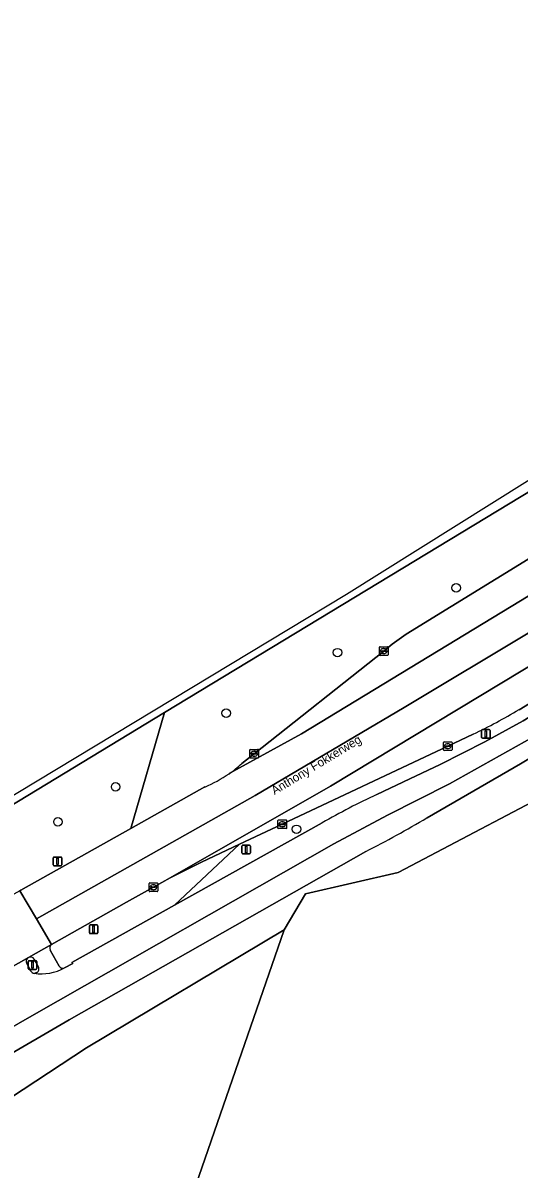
# Model space of a CAD drawing. Extents: x 158132 to 159664, y 385256 to 387218.
# Drawn here: x 158673.7 to 158730.9, y 387074.1 to 387206.2 of the extents above; entities that cross this region are included whole.
import ezdxf

# ---------------------------------------------------------------- set-up
doc = ezdxf.new("R2010")
doc.units = 0
for name, color, linetype in [('IMGEO_Berm_groen', 7, 'Continuous'), ('IMGEO_Boom', 7, 'Continuous'), ('IMGEO_Fietspad_gesloten', 7, 'Continuous'), ('IMGEO_Gemengd_bos', 7, 'Continuous'), ('IMGEO_Groenvoorziening', 7, 'Continuous'), ('IMGEO_Kolk', 7, 'Continuous'), ('IMGEO_Lichtmast', 7, 'Continuous'), ('IMGEO_Openbare_ruimte_label', 7, 'Continuous'), ('IMGEO_Rijbaan_regionaal_gesloten', 7, 'Continuous'), ('IMGEO_Verkeersbordpaal', 7, 'Continuous'), ('IMGEO_Verkeerseiland_open', 7, 'Continuous'), ('IMGEO_Verkeersregelinstallatiepaal', 7, 'Continuous'), ('IMGEO_Voetpad_gesloten', 7, 'Continuous'), ('IMGEO_Voetpad_open', 7, 'Continuous')]:
    doc.layers.add(name, color=color, linetype=linetype)

msp = doc.modelspace()

# ---------------------------------------------------------------- linework, layer by layer
at = {"layer": 'IMGEO_Berm_groen'}
for points in [[(158791.92, 387181.1), (158796.99, 387191.8), (158761.35, 387169.93), (158690.06, 387126.75), (158686.16, 387113.36), (158694.7, 387118.16)], [(158698.94, 387120.87), (158700.39, 387122), (158715.32, 387133.83), (158716.27, 387134.61), (158717.89, 387135.77), (158733.46, 387145.34), (158750.96, 387156.02), (158791.92, 387181.1)], [(158772.34, 387150.79), (158775.89, 387153.01), (158780.92, 387155.97), (158809.62, 387171.75), (158799.54, 387169.08), (158778.35, 387156.07), (158758.93, 387144.19), (158740.98, 387133.23), (158730.91, 387127.07)], [(158714.52, 387117.31), (158718.31, 387119.1), (158721.8, 387120.75), (158726.96, 387123.38), (158731.39, 387125.77), (158772.34, 387150.79)], [(158690.06, 387126.75), (158669.08, 387114.04)], [(158673.36, 387106.21), (158673.51, 387106.27), (158686.16, 387113.36), (158690.06, 387126.75)], [(158725.63, 387124.25), (158722.68, 387122.87), (158703.62, 387113.86), (158698.7, 387111.56), (158691.19, 387104.54), (158708.21, 387114.02)], [(158698.7, 387111.56), (158694.31, 387109.51), (158690.71, 387107.7), (158688.77, 387106.6), (158685.66, 387104.87), (158677.03, 387100.01)], [(158678.54, 387097.3), (158679.47, 387097.81), (158679.38, 387097.95), (158691.19, 387104.54), (158698.7, 387111.56)], [(158676.88, 387099.35), (158677.91, 387097.51)]]:
    msp.add_lwpolyline(points, dxfattribs=at)
for centre, radius, start, end in [((158697.65, 387183.04), 65.1, 295.4546, 300.7185), ((158689.33, 387131.23), 14.14, 305.281, 312.8621), ((158689.33, 387131.21), 14.11, 292.3448, 305.3067), ((158750.8, 387039.92), 85.47, 115.1204, 119.8902), ((158677.37, 387099.59), 0.541, 128.4825, 206.3868), ((158678.34, 387097.77), 0.5, 210.6116, 292.904)]:
    msp.add_arc(centre, radius, start, end, dxfattribs=at)
at = {"layer": 'IMGEO_Boom'}
for centre in [(158723.65, 387141.12), (158709.99, 387133.65), (158697.15, 387126.67), (158684.41, 387118.18), (158677.77, 387114.14), (158705.26, 387113.29)]:
    msp.add_circle(centre, 0.489, dxfattribs=at)
at = {"layer": 'IMGEO_Fietspad_gesloten'}
for points in [[(158709.57, 387111.62), (158715.76, 387114.9), (158722.89, 387118.52), (158732.48, 387123.89), (158776.89, 387150.89), (158823.8, 387176.6), (158822.27, 387178.97), (158818.13, 387176.42), (158809.62, 387171.75), (158780.92, 387155.97), (158775.89, 387153.01), (158772.34, 387150.79), (158731.39, 387125.77), (158726.96, 387123.38), (158721.8, 387120.75), (158718.31, 387119.1), (158714.52, 387117.31)], [(158708.21, 387114.02), (158691.19, 387104.54), (158679.38, 387097.95), (158679.47, 387097.81), (158678.54, 387097.3)], [(158490.61, 386969.27), (158499.21, 386977.39), (158500, 386978.13), (158506.55, 386984.13), (158513.13, 386989.79), (158514.13, 386990.65), (158525.95, 387000), (158529.92, 387003.03), (158546.1, 387014.7), (158573.79, 387032.7), (158595.96, 387046.32), (158640.94, 387072.39), (158675.02, 387091.93), (158709.57, 387111.62)], [(158674.36, 387098.5), (158672.06, 387097.2), (158671.67, 387096.98)], [(158674.64, 387096.95), (158674.17, 387097.81)]]:
    msp.add_lwpolyline(points, dxfattribs=at)
for centre, radius, start, end in [((158750.8, 387039.92), 85.47, 115.1204, 119.8902), ((158674.61, 387098.06), 0.503, 119.8027, 209.4603), ((158675.05, 387097.13), 0.447, 204.2706, 265.9912), ((158675.85, 387102.27), 5.64, 261.5723, 298.4604)]:
    msp.add_arc(centre, radius, start, end, dxfattribs=at)
at = {"layer": 'IMGEO_Gemengd_bos'}
for points in [[(158826.07, 387175.67), (158796.65, 387159.48), (158797.02, 387156.73), (158769.67, 387143.32), (158742.44, 387125.91), (158738.31, 387119.52), (158716.99, 387108.3), (158706.29, 387105.85), (158703.82, 387101.71), (158689.82, 387061.16), (158690.52, 387056.33), (158694.37, 387054.05)], [(158687.81, 387060.41), (158689.82, 387061.16), (158703.82, 387101.71), (158681.04, 387088.11), (158663.51, 387076.57), (158660.41, 387074.96), (158660.01, 387075.7), (158644.04, 387067.33), (158614.63, 387050.48), (158601.87, 387043.7), (158647.81, 386955.65), (158659.44, 386961.72), (158679.26, 386924.45), (158648.61, 386908.46), (158655.38, 386860.52), (158656.73, 386859.94), (158667.25, 386855.4)]]:
    msp.add_lwpolyline(points, dxfattribs=at)
at = {"layer": 'IMGEO_Groenvoorziening'}
for points in [[(158703.82, 387101.71), (158706.29, 387105.85), (158716.99, 387108.3), (158738.31, 387119.52), (158742.44, 387125.91), (158769.67, 387143.32), (158797.02, 387156.73), (158796.65, 387159.48), (158777.85, 387149.12), (158774.25, 387147.16), (158733.5, 387122.28), (158731.08, 387120.83), (158720.3, 387114.61)], [(158713.23, 387110.71), (158679.07, 387091.31), (158676.28, 387089.71), (158659.17, 387079.77)], [(158663.51, 387076.57), (158681.04, 387088.11), (158703.82, 387101.71)]]:
    msp.add_lwpolyline(points, dxfattribs=at)
msp.add_arc((158653.46, 387227.47), 131.17, 297.1084, 300.6309, dxfattribs=at)
at = {"layer": 'IMGEO_Kolk'}
for p, q in [((158714.82, 387133.4), (158714.82, 387134.26)), ((158714.89, 387134.33), (158715.74, 387134.33)), ((158715.12, 387133.87), (158715.52, 387133.87)), ((158715.3, 387134.11), (158715.33, 387134.11)), ((158715.82, 387134.26), (158715.82, 387133.4)), ((158715.74, 387133.33), (158714.89, 387133.33)), ((158715.07, 387133.82), (158715.07, 387133.84)), ((158715.51, 387133.79), (158715.11, 387133.79)), ((158715.33, 387133.55), (158715.3, 387133.55)), ((158715.56, 387133.84), (158715.56, 387133.82)), ((158722.25, 387123.37), (158723.11, 387123.37)), ((158699.89, 387121.57), (158699.89, 387122.43)), ((158699.96, 387122.5), (158700.82, 387122.5)), ((158700.15, 387121.99), (158700.15, 387122.01)), ((158700.19, 387122.04), (158700.59, 387122.04)), ((158700.38, 387122.28), (158700.4, 387122.28)), ((158700.63, 387122.01), (158700.63, 387121.99)), ((158700.89, 387122.43), (158700.89, 387121.57)), ((158722.18, 387122.44), (158722.18, 387123.29)), ((158723.11, 387122.37), (158722.25, 387122.37)), ((158722.44, 387122.86), (158722.44, 387122.87)), ((158722.48, 387122.91), (158722.88, 387122.91)), ((158722.88, 387122.82), (158722.48, 387122.82)), ((158722.67, 387123.15), (158722.69, 387123.15)), ((158722.69, 387122.59), (158722.67, 387122.59)), ((158722.92, 387122.87), (158722.92, 387122.86)), ((158723.18, 387123.29), (158723.18, 387122.44)), ((158700.82, 387121.5), (158699.96, 387121.5)), ((158700.59, 387121.96), (158700.19, 387121.96)), ((158700.4, 387121.72), (158700.38, 387121.72)), ((158703.12, 387113.43), (158703.12, 387114.28)), ((158703.2, 387114.36), (158704.05, 387114.36)), ((158703.61, 387114.14), (158703.64, 387114.14)), ((158704.12, 387114.28), (158704.12, 387113.43)), ((158704.05, 387113.36), (158703.2, 387113.36)), ((158703.38, 387113.85), (158703.38, 387113.86)), ((158703.42, 387113.9), (158703.82, 387113.9)), ((158703.82, 387113.81), (158703.42, 387113.81)), ((158703.63, 387113.58), (158703.61, 387113.58)), ((158703.87, 387113.86), (158703.87, 387113.85)), ((158688.28, 387106.18), (158688.28, 387107.03)), ((158688.35, 387107.1), (158689.2, 387107.1)), ((158688.53, 387106.6), (158688.53, 387106.61)), ((158688.97, 387106.56), (158688.57, 387106.56)), ((158688.58, 387106.65), (158688.97, 387106.65)), ((158688.76, 387106.88), (158688.79, 387106.88)), ((158688.79, 387106.32), (158688.76, 387106.32)), ((158689.02, 387106.61), (158689.02, 387106.6)), ((158689.28, 387107.03), (158689.28, 387106.18)), ((158689.2, 387106.1), (158688.35, 387106.1))]:
    msp.add_line(p, q, dxfattribs=at)
for points in [[(158714.82, 387133.4), (158714.82, 387134.26)], [(158714.89, 387134.33), (158715.74, 387134.33)], [(158715.82, 387134.26), (158715.82, 387133.4)], [(158715.74, 387133.33), (158714.89, 387133.33)], [(158722.25, 387123.37), (158723.11, 387123.37)], [(158699.89, 387121.57), (158699.89, 387122.43)], [(158699.96, 387122.5), (158700.82, 387122.5)], [(158700.89, 387122.43), (158700.89, 387121.57)], [(158722.18, 387122.44), (158722.18, 387123.29)], [(158723.11, 387122.37), (158722.25, 387122.37)], [(158723.18, 387123.29), (158723.18, 387122.44)], [(158700.82, 387121.5), (158699.96, 387121.5)], [(158703.12, 387113.43), (158703.12, 387114.28)], [(158703.2, 387114.36), (158704.05, 387114.36)], [(158704.12, 387114.28), (158704.12, 387113.43)], [(158704.05, 387113.36), (158703.2, 387113.36)], [(158688.28, 387106.18), (158688.28, 387107.03)], [(158688.35, 387107.1), (158689.2, 387107.1)], [(158689.28, 387107.03), (158689.28, 387106.18)], [(158689.2, 387106.1), (158688.35, 387106.1)]]:
    msp.add_lwpolyline(points, dxfattribs=at)
for centre, radius, start, end in [((158714.89, 387134.25), 0.0765, 91.552, 178.448), ((158714.89, 387134.25), 0.0765, 91.552, 178.448), ((158715.12, 387133.83), 0.0403, 85.8775, 175.7526), ((158715.52, 387133.83), 0.0386, 1.7309, 96.639), ((158715.74, 387134.25), 0.0765, 1.552, 88.448), ((158715.74, 387134.25), 0.0765, 1.552, 88.448), ((158714.89, 387133.41), 0.0765, 181.552, 268.448), ((158714.89, 387133.41), 0.0765, 181.552, 268.448), ((158715.11, 387133.82), 0.0366, 178.938, 274.7102), ((158715.52, 387133.83), 0.043, 264.8664, 352.4533), ((158715.74, 387133.41), 0.0765, 271.552, 358.448), ((158715.74, 387133.41), 0.0765, 271.552, 358.448), ((158722.26, 387123.29), 0.0765, 91.552, 178.448), ((158722.26, 387123.29), 0.0765, 91.552, 178.448), ((158723.1, 387123.29), 0.0765, 1.552, 88.448), ((158723.1, 387123.29), 0.0765, 1.552, 88.448), ((158699.97, 387122.43), 0.0765, 91.552, 178.448), ((158699.97, 387122.43), 0.0765, 91.552, 178.448), ((158700.19, 387122), 0.0403, 85.8775, 175.7526), ((158700.19, 387121.99), 0.0366, 178.938, 274.7102), ((158700.59, 387122.01), 0.0386, 1.7309, 96.639), ((158700.59, 387122), 0.043, 264.8664, 352.4533), ((158700.81, 387122.43), 0.0765, 1.552, 88.448), ((158700.81, 387122.43), 0.0765, 1.552, 88.448), ((158722.26, 387122.44), 0.0765, 181.552, 268.448), ((158722.26, 387122.44), 0.0765, 181.552, 268.448), ((158722.48, 387122.87), 0.0403, 85.8775, 175.7526), ((158722.48, 387122.86), 0.0366, 178.938, 274.7102), ((158722.88, 387122.87), 0.0386, 1.7309, 96.639), ((158722.88, 387122.87), 0.043, 264.8664, 352.4533), ((158723.1, 387122.44), 0.0765, 271.552, 358.448), ((158723.1, 387122.44), 0.0765, 271.552, 358.448), ((158699.97, 387121.58), 0.0765, 181.552, 268.448), ((158699.97, 387121.58), 0.0765, 181.552, 268.448), ((158700.81, 387121.58), 0.0765, 271.552, 358.448), ((158700.81, 387121.58), 0.0765, 271.552, 358.448), ((158703.2, 387114.28), 0.0765, 91.552, 178.448), ((158703.2, 387114.28), 0.0765, 91.552, 178.448), ((158704.05, 387114.28), 0.0765, 1.552, 88.448), ((158704.05, 387114.28), 0.0765, 1.552, 88.448), ((158703.2, 387113.43), 0.0765, 181.552, 268.448), ((158703.2, 387113.43), 0.0765, 181.552, 268.448), ((158703.42, 387113.86), 0.0403, 85.8775, 175.7526), ((158703.42, 387113.85), 0.0366, 178.938, 274.7102), ((158703.83, 387113.86), 0.0386, 1.7309, 96.639), ((158703.82, 387113.86), 0.043, 264.8664, 352.4533), ((158704.05, 387113.43), 0.0765, 271.552, 358.448), ((158704.05, 387113.43), 0.0765, 271.552, 358.448), ((158688.35, 387107.03), 0.0765, 91.552, 178.448), ((158688.35, 387107.03), 0.0765, 91.552, 178.448), ((158688.35, 387106.18), 0.0765, 181.552, 268.448), ((158688.35, 387106.18), 0.0765, 181.552, 268.448), ((158688.57, 387106.61), 0.0403, 85.8775, 175.7526), ((158688.57, 387106.6), 0.0366, 178.938, 274.7102), ((158688.98, 387106.61), 0.0386, 1.7309, 96.639), ((158688.98, 387106.6), 0.043, 264.8664, 352.4533), ((158689.2, 387107.03), 0.0765, 1.552, 88.448), ((158689.2, 387107.03), 0.0765, 1.552, 88.448), ((158689.2, 387106.18), 0.0765, 271.552, 358.448), ((158689.2, 387106.18), 0.0765, 271.552, 358.448)]:
    msp.add_arc(centre, radius, start, end, dxfattribs=at)
for centre, major_axis, ratio, start_param, end_param in [((158715.3, 387133.83), (-0.387, 0.002), 0.722429, 4.712389, 7.853982), ((158715.33, 387133.83), (-0.39, 0.002), 0.717154, 1.570796, 4.712389), ((158700.38, 387122), (-0.387, 0.002), 0.722429, 4.712389, 7.853982), ((158700.4, 387122), (-0.39, 0.002), 0.717154, 1.570796, 4.712389), ((158722.67, 387122.87), (-0.387, 0.002), 0.722429, 4.712389, 7.853982), ((158722.69, 387122.87), (-0.39, 0.002), 0.717154, 1.570796, 4.712389), ((158703.61, 387113.86), (-0.387, 0.002), 0.722429, 4.712389, 7.853982), ((158703.63, 387113.86), (-0.39, 0.002), 0.717154, 1.570796, 4.712389), ((158688.76, 387106.6), (-0.387, 0.002), 0.722429, 4.712389, 7.853982), ((158688.79, 387106.6), (-0.39, 0.002), 0.717154, 1.570796, 4.712389)]:
    msp.add_ellipse(centre, major_axis=major_axis, ratio=ratio, start_param=start_param, end_param=end_param, dxfattribs=at)
at = {"layer": 'IMGEO_Lichtmast'}
for p, q in [((158726.58, 387123.88), (158726.58, 387124.68)), ((158726.58, 387124.68), (158726.58, 387123.88)), ((158726.68, 387124.78), (158727.47, 387124.78)), ((158727.47, 387124.78), (158726.68, 387124.78)), ((158727.57, 387124.68), (158727.57, 387123.88)), ((158727.57, 387123.88), (158727.57, 387124.68)), ((158727.47, 387123.78), (158726.68, 387123.78)), ((158726.68, 387123.78), (158727.47, 387123.78)), ((158699.05, 387111.45), (158699.84, 387111.45)), ((158699.84, 387111.45), (158699.05, 387111.45)), ((158698.95, 387110.56), (158698.95, 387111.35)), ((158698.95, 387111.35), (158698.95, 387110.56)), ((158699.84, 387110.46), (158699.05, 387110.46)), ((158699.05, 387110.46), (158699.84, 387110.46)), ((158699.94, 387111.35), (158699.94, 387110.56)), ((158699.94, 387110.56), (158699.94, 387111.35))]:
    msp.add_line(p, q, dxfattribs=at)
for points in [[(158727, 387124.65), (158727.15, 387124.65), (158727.15, 387123.9), (158727, 387123.9), (158727, 387124.65)], [(158699.37, 387111.33), (158699.52, 387111.33), (158699.52, 387110.58), (158699.37, 387110.58), (158699.37, 387111.33)]]:
    msp.add_lwpolyline(points, dxfattribs=at)
for centre, start, end in [((158726.68, 387124.68), 90, 180), ((158726.68, 387124.68), 90, 180), ((158727.47, 387124.68), 0, 90), ((158727.47, 387124.68), 360, 90), ((158726.68, 387123.88), 180, 270), ((158726.68, 387123.88), 180, 270), ((158727.47, 387123.88), 270, 0), ((158727.47, 387123.88), 270, 0), ((158699.05, 387111.35), 90, 180), ((158699.05, 387111.35), 90, 180), ((158699.84, 387111.35), 0, 90), ((158699.84, 387111.35), 360, 90), ((158699.05, 387110.56), 180, 270), ((158699.05, 387110.56), 180, 270), ((158699.84, 387110.56), 270, 0), ((158699.84, 387110.56), 270, 0)]:
    msp.add_arc(centre, 0.1, start, end, dxfattribs=at)
at = {"layer": 'IMGEO_Rijbaan_regionaal_gesloten'}
for points in [[(158668.65, 387114.8), (158669.08, 387114.04), (158690.06, 387126.75), (158761.35, 387169.93), (158796.99, 387191.8), (158809.69, 387199.41), (158813.77, 387201.92), (158813.94, 387202), (158817.67, 387203.77), (158816.23, 387206.23), (158711.03, 387140.33)], [(158826.64, 387189.6), (158824.7, 387192.58), (158800.45, 387177.82), (158765.96, 387156.73), (158732.32, 387136.14), (158717.67, 387127.33), (158700.49, 387117.19), (158675.29, 387102.95), (158677.03, 387100.01), (158685.66, 387104.87), (158688.77, 387106.6), (158690.71, 387107.7), (158709.19, 387118.27), (158750.91, 387143.43), (158788.89, 387166.58)], [(158671.48, 387096.87), (158671.67, 387096.98), (158672.06, 387097.2), (158674.36, 387098.5), (158677.03, 387100.01), (158675.29, 387102.95), (158673.36, 387106.21), (158670.77, 387104.76), (158668.48, 387103.47), (158668.1, 387103.26), (158665.43, 387101.78), (158665.39, 387101.74), (158634.99, 387084.15), (158636.6, 387081.34), (158638.36, 387078.28), (158640.95, 387079.72), (158641.05, 387079.78), (158643.71, 387081.28), (158653.11, 387086.57)]]:
    msp.add_lwpolyline(points, close=True, dxfattribs=at)
for points in [[(158822.71, 387195.63), (158820.74, 387198.66), (158817.24, 387196.51), (158817.15, 387196.45), (158813.1, 387193.96), (158813.01, 387193.91), (158791.92, 387181.1), (158750.96, 387156.02), (158733.46, 387145.34), (158717.89, 387135.77), (158716.27, 387134.61), (158715.32, 387133.83), (158700.39, 387122), (158698.94, 387120.87)], [(158697.49, 387119.7), (158705.84, 387124.3), (158734.09, 387141.45), (158796, 387179.3), (158822.71, 387195.63)], [(158824.7, 387192.58), (158822.71, 387195.63), (158796, 387179.3), (158734.09, 387141.45), (158705.84, 387124.3), (158697.49, 387119.7)], [(158694.7, 387118.16), (158686.16, 387113.36), (158673.51, 387106.27), (158673.36, 387106.21), (158675.29, 387102.95), (158700.49, 387117.19), (158717.67, 387127.33), (158732.32, 387136.14), (158765.96, 387156.73), (158800.45, 387177.82), (158824.7, 387192.58)], [(158829.18, 387185.48), (158829.32, 387185.49), (158826.64, 387189.6), (158788.89, 387166.58), (158750.91, 387143.43), (158709.19, 387118.27), (158690.71, 387107.7), (158694.31, 387109.51), (158698.7, 387111.56), (158703.62, 387113.86), (158722.68, 387122.87), (158725.63, 387124.25)], [(158730.91, 387127.07), (158740.98, 387133.23), (158758.93, 387144.19), (158778.35, 387156.07), (158799.54, 387169.08), (158801.46, 387170.27), (158819.41, 387181.21), (158820.49, 387181.92), (158824.76, 387184.29), (158824.89, 387184.35)]]:
    msp.add_lwpolyline(points, dxfattribs=at)
for centre, radius, start, end in [((158697.65, 387183.04), 65.1, 295.4546, 300.7185), ((158689.33, 387131.23), 14.14, 305.281, 312.8621), ((158689.33, 387131.21), 14.11, 292.3448, 305.3067)]:
    msp.add_arc(centre, radius, start, end, dxfattribs=at)
at = {"layer": 'IMGEO_Verkeersbordpaal'}
for p, q in [((158677.31, 387110.09), (158678.1, 387110.09)), ((158678.1, 387110.09), (158677.31, 387110.09)), ((158677.21, 387109.19), (158677.21, 387109.99)), ((158677.21, 387109.99), (158677.21, 387109.19)), ((158678.1, 387109.09), (158677.31, 387109.09)), ((158677.31, 387109.09), (158678.1, 387109.09)), ((158678.2, 387109.99), (158678.2, 387109.19)), ((158678.2, 387109.19), (158678.2, 387109.99)), ((158681.39, 387101.36), (158681.39, 387102.16)), ((158681.39, 387102.16), (158681.39, 387101.36)), ((158681.49, 387102.26), (158682.27, 387102.26)), ((158682.27, 387102.26), (158681.49, 387102.26)), ((158682.37, 387102.16), (158682.37, 387101.36)), ((158682.37, 387101.36), (158682.37, 387102.16)), ((158682.27, 387101.26), (158681.49, 387101.26)), ((158681.49, 387101.26), (158682.27, 387101.26))]:
    msp.add_line(p, q, dxfattribs=at)
for points in [[(158677.63, 387109.96), (158677.78, 387109.96), (158677.78, 387109.21), (158677.63, 387109.21), (158677.63, 387109.96)], [(158681.8, 387102.14), (158681.96, 387102.14), (158681.96, 387101.39), (158681.8, 387101.39), (158681.8, 387102.14)]]:
    msp.add_lwpolyline(points, dxfattribs=at)
for centre, start, end in [((158677.31, 387109.99), 90, 180), ((158677.31, 387109.99), 90, 180), ((158678.1, 387109.99), 0, 90), ((158678.1, 387109.99), 360, 90), ((158677.31, 387109.19), 180, 270), ((158677.31, 387109.19), 180, 270), ((158678.1, 387109.19), 270, 0), ((158678.1, 387109.19), 270, 0), ((158681.49, 387102.16), 90, 180), ((158681.49, 387102.16), 90, 180), ((158682.27, 387102.16), 0, 90), ((158682.27, 387102.16), 360, 90), ((158681.49, 387101.36), 180, 270), ((158681.49, 387101.36), 180, 270), ((158682.27, 387101.36), 270, 0), ((158682.27, 387101.36), 270, 0)]:
    msp.add_arc(centre, 0.1, start, end, dxfattribs=at)
at = {"layer": 'IMGEO_Verkeerseiland_open'}
for points in [[(158675.52, 387097.41), (158675.04, 387098.33)], [(158674.17, 387097.81), (158674.64, 387096.95)], [(158675.02, 387096.68), (158675.33, 387096.76)]]:
    msp.add_lwpolyline(points, dxfattribs=at)
for centre, radius, start, end in [((158674.61, 387098.06), 0.503, 119.8027, 209.4603), ((158674.6, 387098.02), 0.532, 35.0069, 116.9604), ((158675.05, 387097.13), 0.447, 204.2706, 265.9912), ((158675.11, 387097.18), 0.472, 298.7718, 29.4312)]:
    msp.add_arc(centre, radius, start, end, dxfattribs=at)
at = {"layer": 'IMGEO_Verkeersregelinstallatiepaal'}
for p, q in [((158674.34, 387097.24), (158674.34, 387098.04)), ((158674.34, 387098.04), (158674.34, 387097.24)), ((158674.44, 387098.14), (158675.22, 387098.14)), ((158675.22, 387098.14), (158674.44, 387098.14)), ((158675.22, 387097.14), (158674.44, 387097.14)), ((158674.44, 387097.14), (158675.22, 387097.14)), ((158675.32, 387098.04), (158675.32, 387097.24)), ((158675.32, 387097.24), (158675.32, 387098.04))]:
    msp.add_line(p, q, dxfattribs=at)
msp.add_lwpolyline([(158674.75, 387098.02), (158674.9, 387098.02), (158674.9, 387097.27), (158674.75, 387097.27), (158674.75, 387098.02)], dxfattribs=at)
for centre, start, end in [((158674.44, 387098.04), 90, 180), ((158674.44, 387098.04), 90, 180), ((158674.44, 387097.24), 180, 270), ((158674.44, 387097.24), 180, 270), ((158675.22, 387098.04), 0, 90), ((158675.22, 387098.04), 360, 90), ((158675.22, 387097.24), 270, 0), ((158675.22, 387097.24), 270, 0)]:
    msp.add_arc(centre, 0.1, start, end, dxfattribs=at)
at = {"layer": 'IMGEO_Voetpad_gesloten'}
for points in [[(158774.25, 387147.16), (158777.85, 387149.12), (158796.65, 387159.48), (158826.07, 387175.67), (158824.96, 387177.23), (158823.8, 387176.6), (158776.89, 387150.89), (158732.48, 387123.89), (158722.89, 387118.52), (158715.76, 387114.9), (158709.57, 387111.62), (158675.02, 387091.93), (158640.94, 387072.39), (158595.96, 387046.32), (158573.79, 387032.7), (158546.1, 387014.7), (158529.92, 387003.03), (158525.95, 387000), (158514.13, 386990.65), (158513.13, 386989.79), (158506.55, 386984.13), (158500, 386978.13), (158499.21, 386977.39), (158490.61, 386969.27)], [(158720.3, 387114.61), (158731.08, 387120.83), (158733.5, 387122.28), (158774.25, 387147.16)], [(158490.27, 386966.83), (158500, 386976.11), (158500.23, 386976.33), (158507.53, 386983.02), (158514.05, 386988.61), (158515.07, 386989.48), (158528.38, 387000), (158530.82, 387001.85), (158546.88, 387013.42), (158565.98, 387025.84), (158566.37, 387026.1), (158567.92, 387027.11), (158572.64, 387030.18), (158574.56, 387031.33), (158596.69, 387045), (158644.09, 387072.48), (158644.61, 387071.6), (158658.37, 387079.32), (158658.74, 387078.62), (158659.55, 387079.09), (158659.17, 387079.77), (158676.28, 387089.71), (158679.07, 387091.31), (158713.23, 387110.71)]]:
    msp.add_lwpolyline(points, dxfattribs=at)
msp.add_arc((158653.46, 387227.47), 131.17, 297.1084, 300.6309, dxfattribs=at)
at = {"layer": 'IMGEO_Voetpad_open'}
for points in [[(158677.03, 387100.01), (158674.36, 387098.5)], [(158675.04, 387098.33), (158675.52, 387097.41)], [(158677.91, 387097.51), (158676.88, 387099.35)], [(158675.33, 387096.76), (158675.02, 387096.68)]]:
    msp.add_lwpolyline(points, dxfattribs=at)
for centre, radius, start, end in [((158677.37, 387099.59), 0.541, 128.4825, 206.3868), ((158674.6, 387098.02), 0.532, 35.0069, 116.9604), ((158675.85, 387102.27), 5.64, 261.5723, 298.4604), ((158675.11, 387097.18), 0.472, 298.7718, 29.4312), ((158678.34, 387097.77), 0.5, 210.6116, 292.904)]:
    msp.add_arc(centre, radius, start, end, dxfattribs=at)

# ---------------------------------------------------------------- texts
at = {"layer": 'IMGEO_Openbare_ruimte_label'}
msp.add_text('Anthony Fokkerweg', height=1, rotation=31.2095, dxfattribs=at).set_placement((158702.73, 387117.23))

doc.saveas('drawing.dxf')
